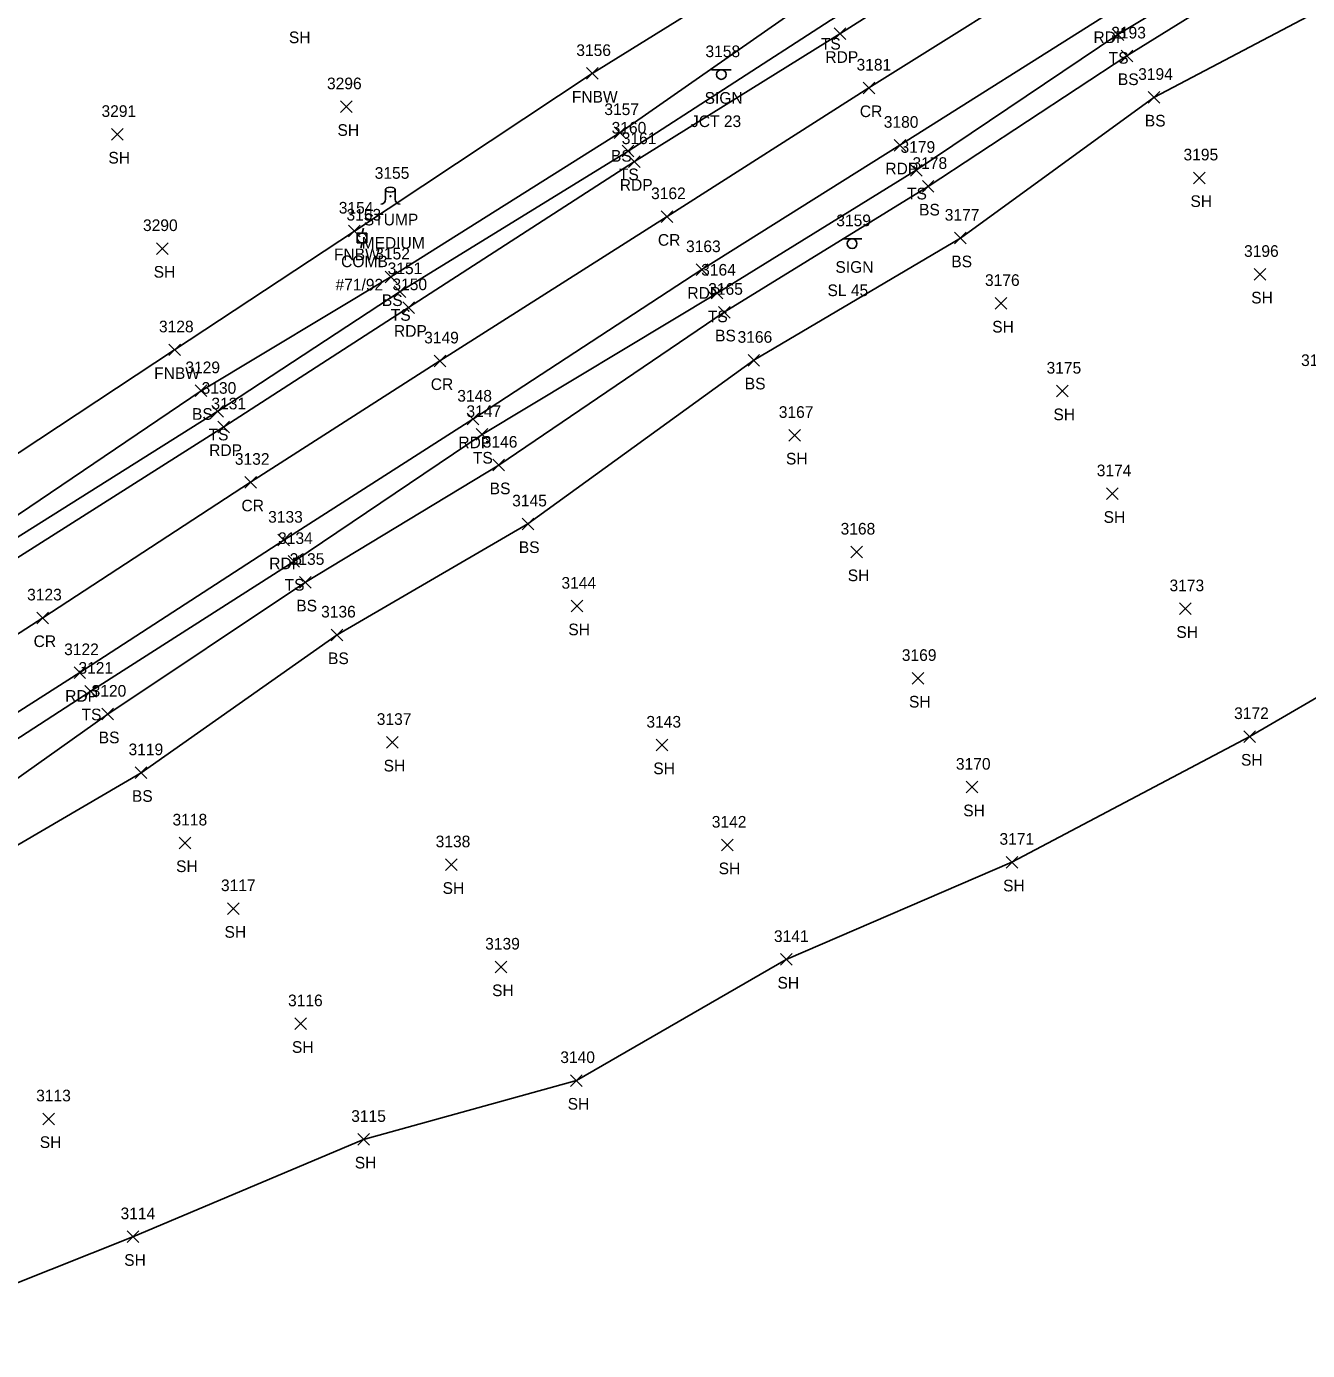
# Model space of a CAD drawing. Extents: x 1443590 to 1445966, y 578314 to 580556.
# Drawn here: x 1443728.1 to 1443948, y 578518.2 to 578745.5 of the extents above; entities that cross this region are included whole.
import ezdxf

# ---------------------------------------------------------------- set-up
doc = ezdxf.new("R2010")
doc.units = 0
for name, color, linetype in [('L_A', 7, 'Continuous'), ('L_C', 7, 'Continuous'), ('L_I', 7, 'Continuous'), ('L_TIC', 7, 'Continuous'), ('LELB', 7, 'Continuous'), ('LFNC', 7, 'Continuous'), ('LSOGP', 7, 'Continuous'), ('LTS', 7, 'Continuous'), ('P_A', 7, 'Continuous'), ('P_I', 7, 'Continuous'), ('P_TIC', 7, 'Continuous'), ('PET', 7, 'Continuous'), ('PRC', 7, 'Continuous'), ('S_A', 7, 'Continuous'), ('S_C', 7, 'Continuous'), ('S_I', 7, 'Continuous'), ('SSGN', 7, 'Continuous'), ('U_A', 7, 'Continuous'), ('U_C', 7, 'Continuous'), ('U_I', 7, 'Continuous'), ('UP', 7, 'Continuous')]:
    doc.layers.add(name, color=color, linetype=linetype)

msp = doc.modelspace()

# ---------------------------------------------------------------- linework, layer by layer
at = {"layer": 'L_TIC'}
for points in [[(1443914.45, 578743.08), (1443916.45, 578745.08)], [(1443916.45, 578743.08), (1443914.45, 578745.08)], [(1443916, 578739.41), (1443918, 578741.41)], [(1443918, 578739.41), (1443916, 578741.41)], [(1443824.24, 578736.4), (1443826.24, 578738.4)], [(1443826.24, 578736.4), (1443824.24, 578738.4)], [(1443920.62, 578732.3), (1443922.62, 578734.3)], [(1443922.62, 578732.3), (1443920.62, 578734.3)], [(1443782.01, 578730.69), (1443784.01, 578732.69)], [(1443784.01, 578730.69), (1443782.01, 578732.69)], [(1443742.69, 578725.94), (1443744.69, 578727.94)], [(1443744.69, 578725.94), (1443742.69, 578727.94)], [(1443829, 578726.26), (1443831, 578728.26)], [(1443831, 578726.26), (1443829, 578728.26)], [(1443830.38, 578723.08), (1443832.38, 578725.08)], [(1443832.38, 578723.08), (1443830.38, 578725.08)], [(1443879.84, 578719.78), (1443881.84, 578721.78)], [(1443881.84, 578719.78), (1443879.84, 578721.78)], [(1443928.4, 578718.48), (1443930.4, 578720.48)], [(1443930.4, 578718.48), (1443928.4, 578720.48)], [(1443881.88, 578717.02), (1443883.88, 578719.02)], [(1443883.88, 578717.02), (1443881.88, 578719.02)], [(1443783.42, 578709.35), (1443785.42, 578711.35)], [(1443785.42, 578709.35), (1443783.42, 578711.35)], [(1443887.41, 578708.13), (1443889.41, 578710.13)], [(1443889.41, 578708.13), (1443887.41, 578710.13)], [(1443750.46, 578706.35), (1443752.46, 578708.35)], [(1443752.46, 578706.35), (1443750.46, 578708.35)], [(1443938.83, 578701.92), (1443940.83, 578703.92)], [(1443940.83, 578701.92), (1443938.83, 578703.92)], [(1443789.68, 578701.48), (1443791.68, 578703.48)], [(1443791.68, 578701.48), (1443789.68, 578703.48)], [(1443791.24, 578698.95), (1443793.24, 578700.95)], [(1443793.24, 578698.95), (1443791.24, 578700.95)], [(1443845.66, 578698.7), (1443847.66, 578700.7)], [(1443847.66, 578698.7), (1443845.66, 578700.7)], [(1443846.87, 578695.41), (1443848.87, 578697.41)], [(1443848.87, 578695.41), (1443846.87, 578697.41)], [(1443894.38, 578696.93), (1443896.38, 578698.93)], [(1443896.38, 578696.93), (1443894.38, 578698.93)], [(1443752.55, 578688.96), (1443754.55, 578690.96)], [(1443754.55, 578688.96), (1443752.55, 578690.96)], [(1443851.96, 578687.17), (1443853.96, 578689.17)], [(1443853.96, 578687.17), (1443851.96, 578689.17)], [(1443757.09, 578681.95), (1443759.09, 578683.95)], [(1443759.09, 578681.95), (1443757.09, 578683.95)], [(1443904.9, 578681.88), (1443906.9, 578683.88)], [(1443906.9, 578681.88), (1443904.9, 578683.88)], [(1443759.96, 578678.42), (1443761.96, 578680.42)], [(1443761.96, 578678.42), (1443759.96, 578680.42)], [(1443805.33, 578674.43), (1443807.33, 578676.43)], [(1443807.33, 578674.43), (1443805.33, 578676.43)], [(1443858.98, 578674.28), (1443860.98, 578676.28)], [(1443860.98, 578674.28), (1443858.98, 578676.28)], [(1443808.17, 578669.17), (1443810.17, 578671.17)], [(1443810.17, 578669.17), (1443808.17, 578671.17)], [(1443913.5, 578664.26), (1443915.5, 578666.26)], [(1443915.5, 578664.26), (1443913.5, 578666.26)], [(1443813.18, 578659.08), (1443815.18, 578661.08)], [(1443815.18, 578659.08), (1443813.18, 578661.08)], [(1443869.59, 578654.25), (1443871.59, 578656.25)], [(1443871.59, 578654.25), (1443869.59, 578656.25)], [(1443773.01, 578652.63), (1443775.01, 578654.63)], [(1443775.01, 578652.63), (1443773.01, 578654.63)], [(1443774.99, 578649.05), (1443776.99, 578651.05)], [(1443776.99, 578649.05), (1443774.99, 578651.05)], [(1443821.63, 578644.96), (1443823.63, 578646.96)], [(1443823.63, 578644.96), (1443821.63, 578646.96)], [(1443925.99, 578644.52), (1443927.99, 578646.52)], [(1443927.99, 578644.52), (1443925.99, 578646.52)], [(1443780.43, 578640.01), (1443782.43, 578642.01)], [(1443782.43, 578640.01), (1443780.43, 578642.01)], [(1443880.11, 578632.56), (1443882.11, 578634.56)], [(1443882.11, 578632.56), (1443880.11, 578634.56)], [(1443738.16, 578630.36), (1443740.16, 578632.36)], [(1443740.16, 578630.36), (1443738.16, 578632.36)], [(1443741.08, 578626.42), (1443743.08, 578628.42)], [(1443743.08, 578626.42), (1443741.08, 578628.42)], [(1443937.08, 578622.58), (1443939.08, 578624.58)], [(1443939.08, 578622.58), (1443937.08, 578624.58)], [(1443789.93, 578621.58), (1443791.93, 578623.58)], [(1443791.93, 578621.58), (1443789.93, 578623.58)], [(1443836.21, 578621.11), (1443838.21, 578623.11)], [(1443838.21, 578621.11), (1443836.21, 578623.11)], [(1443746.78, 578616.37), (1443748.78, 578618.37)], [(1443748.78, 578616.37), (1443746.78, 578618.37)], [(1443889.41, 578613.89), (1443891.41, 578615.89)], [(1443891.41, 578613.89), (1443889.41, 578615.89)], [(1443754.31, 578604.31), (1443756.31, 578606.31)], [(1443756.31, 578604.31), (1443754.31, 578606.31)], [(1443847.43, 578603.94), (1443849.43, 578605.94)], [(1443849.43, 578603.94), (1443847.43, 578605.94)], [(1443800.05, 578600.57), (1443802.05, 578602.57)], [(1443802.05, 578600.57), (1443800.05, 578602.57)], [(1443896.25, 578601), (1443898.25, 578603)], [(1443898.25, 578601), (1443896.25, 578603)], [(1443762.62, 578593.04), (1443764.62, 578595.04)], [(1443764.62, 578593.04), (1443762.62, 578595.04)], [(1443857.53, 578584.31), (1443859.53, 578586.31)], [(1443859.53, 578584.31), (1443857.53, 578586.31)], [(1443808.55, 578583.01), (1443810.55, 578585.01)], [(1443810.55, 578583.01), (1443808.55, 578585.01)], [(1443774.19, 578573.28), (1443776.19, 578575.28)], [(1443776.19, 578573.28), (1443774.19, 578575.28)], [(1443821.52, 578563.53), (1443823.52, 578565.53)], [(1443823.52, 578563.53), (1443821.52, 578565.53)], [(1443730.91, 578556.95), (1443732.91, 578558.95)], [(1443732.91, 578556.95), (1443730.91, 578558.95)], [(1443784.98, 578553.43), (1443786.98, 578555.43)], [(1443786.98, 578553.43), (1443784.98, 578555.43)], [(1443745.4, 578536.72), (1443747.4, 578538.72)], [(1443747.4, 578536.72), (1443745.4, 578538.72)]]:
    msp.add_lwpolyline(points, dxfattribs=at)
at = {"layer": 'LELB'}
for points in [[(1443615.53, 578549.09), (1443647.15, 578571.87), (1443656.71, 578577.24), (1443699.78, 578605.86), (1443739.16, 578631.36), (1443774.01, 578653.63), (1443806.33, 578675.43), (1443846.66, 578699.7), (1443880.84, 578720.78), (1443915.45, 578744.08), (1443953.64, 578767.01), (1443986.4, 578787.39), (1444018.89, 578809.07), (1444030.21, 578814.65), (1444042.78, 578823.31), (1444045.84, 578825.91), (1444071.11, 578843.04), (1444083.63, 578848.63), (1444101.33, 578858.93), (1444132.81, 578873.64), (1444159.48, 578890.92), (1444189.04, 578910.16), (1444210.73, 578922.71), (1444214.87, 578926.32)], [(1443598.08, 578578.97), (1443630.15, 578597.86), (1443636.56, 578601.95), (1443682.3, 578633.7), (1443721.18, 578657.98), (1443758.09, 578682.95), (1443790.68, 578702.48), (1443830, 578727.26), (1443864.08, 578751.06), (1443899.99, 578773.27), (1443935.63, 578795.8), (1443970.37, 578818.04), (1444002.82, 578839.42), (1444013.71, 578847.8), (1444018.65, 578851.29), (1444030.07, 578858.77)], [(1443617.38, 578545.93), (1443649.59, 578568.34), (1443659.37, 578572.13), (1443703.15, 578599.79), (1443742.08, 578627.42), (1443775.99, 578650.05), (1443809.17, 578670.17), (1443847.87, 578696.41), (1443882.88, 578718.02), (1443917, 578740.41), (1443955.43, 578764.28), (1443988.08, 578784.83), (1444022, 578804.82), (1444030.48, 578811.54), (1444041.56, 578818.92), (1444047.79, 578822.82), (1444063.67, 578832.31)], [(1443599.26, 578576.43), (1443630.85, 578596.23), (1443637.73, 578600.06), (1443684.16, 578630.63), (1443722.9, 578655.5), (1443760.96, 578679.42), (1443792.24, 578699.95), (1443831.38, 578724.08), (1443866.05, 578746.5), (1443902.3, 578768.55), (1443938.52, 578791.48), (1443973.38, 578813.08)], [(1443707.24, 578593.68), (1443747.78, 578617.37), (1443781.43, 578641.01), (1443814.18, 578660.08), (1443852.96, 578688.17), (1443888.41, 578709.13), (1443921.62, 578733.3), (1443961.2, 578754.18), (1443994.65, 578773), (1444028.44, 578794.43), (1444032.53, 578801.75)]]:
    msp.add_lwpolyline(points, dxfattribs=at)
at = {"layer": 'LFNC'}
msp.add_lwpolyline([(1443632.19, 578609.42), (1443678.23, 578640.34), (1443716.84, 578665.76), (1443753.55, 578689.96), (1443784.42, 578710.35), (1443825.24, 578737.4), (1443860.1, 578759.1), (1443895.87, 578781.95), (1443931.05, 578803.95), (1443965.66, 578826.05), (1443995.74, 578844.91)], dxfattribs=at)
at = {"layer": 'LSOGP'}
msp.add_lwpolyline([(1443697.37, 578518.18), (1443746.4, 578537.72), (1443785.98, 578554.43), (1443822.53, 578564.53), (1443858.53, 578585.31), (1443897.25, 578602), (1443938.08, 578623.58), (1443972.29, 578643.52)], dxfattribs=at)
at = {"layer": 'LTS'}
for p, q in [((1443789.75, 578717.46), (1443789.75, 578715.8)), ((1443790.58, 578716.32), (1443790.58, 578716.32)), ((1443790.58, 578716.32), (1443790.58, 578716.32)), ((1443790.58, 578716.3), (1443790.58, 578716.3)), ((1443791.42, 578717.3), (1443791.42, 578717.46)), ((1443791.42, 578717.46), (1443791.42, 578715.8))]:
    msp.add_line(p, q, dxfattribs=at)
msp.add_circle((1443790.58, 578716.32), 0.0833, dxfattribs=at)
for centre, start, end in [((1443788.92, 578715.8), 270, 360), ((1443792.25, 578715.8), 180, 270)]:
    msp.add_arc(centre, 0.833, start, end, dxfattribs=at)
msp.add_ellipse((1443790.58, 578717.46), major_axis=(-0.833, 0), ratio=0.5, dxfattribs=at)
at = {"layer": 'P_TIC'}
for points in [[(1443866.74, 578743.22), (1443868.74, 578745.22)], [(1443868.74, 578743.22), (1443866.74, 578745.22)], [(1443871.72, 578733.91), (1443873.72, 578735.91)], [(1443873.72, 578733.91), (1443871.72, 578735.91)], [(1443877.04, 578724.08), (1443879.04, 578726.08)], [(1443879.04, 578724.08), (1443877.04, 578726.08)], [(1443831.46, 578721.27), (1443833.46, 578723.27)], [(1443833.46, 578721.27), (1443831.46, 578723.27)], [(1443837.06, 578711.83), (1443839.06, 578713.83)], [(1443839.06, 578711.83), (1443837.06, 578713.83)], [(1443843.06, 578702.73), (1443845.06, 578704.73)], [(1443845.06, 578702.73), (1443843.06, 578704.73)], [(1443792.7, 578696.2), (1443794.7, 578698.2)], [(1443794.7, 578696.2), (1443792.7, 578698.2)], [(1443798.08, 578687.06), (1443800.08, 578689.06)], [(1443800.08, 578687.06), (1443798.08, 578689.06)], [(1443803.75, 578677.07), (1443805.75, 578679.07)], [(1443805.75, 578677.07), (1443803.75, 578679.07)], [(1443760.98, 578675.74), (1443762.98, 578677.74)], [(1443762.98, 578675.74), (1443760.98, 578677.74)], [(1443765.58, 578666.23), (1443767.58, 578668.23)], [(1443767.58, 578666.23), (1443765.58, 578668.23)], [(1443771.29, 578656.29), (1443773.29, 578658.29)], [(1443773.29, 578656.29), (1443771.29, 578658.29)], [(1443729.92, 578642.94), (1443731.92, 578644.94)], [(1443731.92, 578642.94), (1443729.92, 578644.94)], [(1443736.28, 578633.55), (1443738.28, 578635.55)], [(1443738.28, 578633.55), (1443736.28, 578635.55)]]:
    msp.add_lwpolyline(points, dxfattribs=at)
at = {"layer": 'PET'}
for points in [[(1443601.36, 578573.38), (1443632.23, 578593.39), (1443639.99, 578598.09), (1443685.58, 578628.02), (1443724.74, 578653.09), (1443761.98, 578676.74), (1443793.7, 578697.2), (1443832.46, 578722.27), (1443867.74, 578744.22), (1443903.66, 578767.03), (1443939.74, 578789.58), (1443974.31, 578811.25), (1444005.54, 578830.37), (1444024.78, 578842.02), (1444070.83, 578869.64), (1444088.82, 578880.14), (1444118.02, 578897.28), (1444147.48, 578914.76), (1444176.13, 578931.32), (1444203.82, 578947.29), (1444208.88, 578939.04), (1444214.07, 578930.35)], [(1443612.4, 578554.37), (1443645.04, 578575.45), (1443657.24, 578583.2), (1443697.44, 578609.18), (1443737.28, 578634.55), (1443772.29, 578657.29), (1443804.75, 578678.07), (1443844.06, 578703.73), (1443878.04, 578725.08), (1443913.76, 578747.61), (1443950.95, 578770.86), (1443984.55, 578791.67), (1444017.37, 578812.19), (1444029.71, 578820.04), (1444042.88, 578828.09), (1444081.78, 578851.73), (1444099.65, 578862.29), (1444128.94, 578879.48), (1444156.82, 578896.17), (1444186.94, 578914.09), (1444214.07, 578930.35)]]:
    msp.add_lwpolyline(points, dxfattribs=at)
at = {"layer": 'PRC'}
msp.add_lwpolyline([(1443607.19, 578563.71), (1443645.74, 578588.68), (1443691.8, 578618.64), (1443730.92, 578643.94), (1443766.58, 578667.23), (1443799.08, 578688.06), (1443838.06, 578712.83), (1443872.72, 578734.91), (1443908.54, 578757.41), (1443944.72, 578780.26), (1443979.55, 578801.84), (1444011.31, 578821.61), (1444031.47, 578833.87), (1444076.05, 578860.79), (1444093.92, 578871.67), (1444123.23, 578888.92), (1444152.19, 578905.95), (1444180.96, 578922.73), (1444208.88, 578939.04)], dxfattribs=at)
at = {"layer": 'SSGN'}
for p, q in [((1443845.72, 578738.05), (1443849.06, 578738.05)), ((1443847.37, 578737.22), (1443847.37, 578737.22)), ((1443868.18, 578709.03), (1443871.51, 578709.03)), ((1443869.83, 578708.2), (1443869.83, 578708.2))]:
    msp.add_line(p, q, dxfattribs=at)
for centre in [(1443847.37, 578737.22), (1443869.83, 578708.2)]:
    msp.add_circle(centre, 0.833, dxfattribs=at)
at = {"layer": 'UP'}
for p, q in [((1443785.98, 578710.82), (1443785.73, 578709.99)), ((1443784.9, 578708.32), (1443784.9, 578709.99)), ((1443784.9, 578709.99), (1443786.56, 578709.99)), ((1443785.73, 578709.15), (1443785.73, 578709.15)), ((1443786.56, 578709.99), (1443786.56, 578708.32)), ((1443786.56, 578708.32), (1443784.9, 578708.32)), ((1443785.48, 578707.49), (1443785.73, 578708.32))]:
    msp.add_line(p, q, dxfattribs=at)
msp.add_circle((1443785.73, 578709.15), 0.833, dxfattribs=at)

# ---------------------------------------------------------------- texts
at = {"layer": 'L_A'}
for s, p in [('SH', (1443773.16, 578742.6)), ('TS', (1443864.46, 578741.5)), ('TS', (1443913.86, 578739.08)), ('BS', (1443915.44, 578735.41)), ('FNBW', (1443821.72, 578732.4)), ('BS', (1443920.06, 578728.3)), ('SH', (1443781.5, 578726.69)), ('BS', (1443828.44, 578722.26)), ('SH', (1443742.18, 578721.94)), ('TS', (1443829.79, 578719.08)), ('TS', (1443879.25, 578715.78)), ('SH', (1443927.89, 578714.48)), ('STUMP', (1443786.01, 578711.32)), ('BS', (1443881.32, 578713.02)), ('FNBW', (1443780.89, 578705.35)), ('BS', (1443886.85, 578704.13)), ('SH', (1443749.95, 578702.35)), ('BS', (1443789.12, 578697.48)), ('SH', (1443938.32, 578697.92)), ('TS', (1443790.65, 578694.95)), ('TS', (1443845.07, 578694.7)), ('SH', (1443893.87, 578692.93)), ('BS', (1443846.31, 578691.41)), ('FNBW', (1443750.03, 578684.96)), ('BS', (1443851.4, 578683.17)), ('BS', (1443756.53, 578677.95)), ('SH', (1443904.38, 578677.88)), ('TS', (1443759.37, 578674.42)), ('TS', (1443804.74, 578670.43)), ('SH', (1443858.47, 578670.28)), ('BS', (1443807.62, 578665.17)), ('SH', (1443912.99, 578660.26)), ('BS', (1443812.62, 578655.08)), ('SH', (1443869.08, 578650.25)), ('TS', (1443772.42, 578648.63)), ('BS', (1443774.43, 578645.05)), ('SH', (1443821.12, 578640.96)), ('SH', (1443925.48, 578640.52)), ('BS', (1443779.88, 578636.01)), ('SH', (1443879.59, 578628.56)), ('TS', (1443737.57, 578626.36)), ('BS', (1443740.52, 578622.42)), ('SH', (1443936.57, 578618.58)), ('SH', (1443789.42, 578617.58)), ('SH', (1443835.7, 578617.11)), ('BS', (1443746.22, 578612.37)), ('SH', (1443888.9, 578609.89)), ('SH', (1443753.8, 578600.31)), ('SH', (1443846.92, 578599.94)), ('SH', (1443799.54, 578596.57)), ('SH', (1443895.74, 578597)), ('SH', (1443762.11, 578589.04)), ('SH', (1443857.02, 578580.31)), ('SH', (1443808.04, 578579.01)), ('SH', (1443773.68, 578569.28)), ('SH', (1443821.01, 578559.53)), ('SH', (1443730.4, 578552.95)), ('SH', (1443784.47, 578549.43)), ('SH', (1443744.89, 578532.72))]:
    msp.add_text(s, height=2, dxfattribs=at).set_placement(p)
at = {"layer": 'L_C'}
msp.add_text('MEDIUM', height=2, dxfattribs=at).set_placement((1443785.64, 578707.32))
at = {"layer": 'L_I'}
for s, p in [('3193', (1443914.3, 578743.41)), ('3156', (1443822.49, 578740.4)), ('3194', (1443918.92, 578736.3)), ('3296', (1443779.7, 578734.69)), ('3291', (1443741, 578729.94)), ('3157', (1443827.3, 578730.26)), ('3160', (1443828.55, 578727.08)), ('3179', (1443878.14, 578723.78)), ('3195', (1443926.71, 578722.48)), ('3178', (1443880.19, 578721.02)), ('3155', (1443787.89, 578719.32)), ('3154', (1443781.72, 578713.35)), ('3177', (1443885.72, 578712.13)), ('3290', (1443748.12, 578710.35)), ('3152', (1443787.98, 578705.48)), ('3196', (1443937.09, 578705.92)), ('3151', (1443790.11, 578702.95)), ('3164', (1443843.92, 578702.7)), ('3176', (1443892.63, 578700.93)), ('3165', (1443845.13, 578699.41)), ('3128', (1443750.86, 578692.96)), ('3166', (1443850.17, 578691.17)), ('3129', (1443755.39, 578685.95)), ('3197', (1443946.88, 578687.18)), ('3175', (1443903.2, 578685.88)), ('3130', (1443758.18, 578682.42)), ('3147', (1443803.64, 578678.43)), ('3167', (1443857.24, 578678.28)), ('3146', (1443806.43, 578673.17)), ('3174', (1443911.81, 578668.26)), ('3145', (1443811.49, 578663.08)), ('3134', (1443771.31, 578656.63)), ('3168', (1443867.85, 578658.25)), ('3135', (1443773.3, 578653.05)), ('3144', (1443819.94, 578648.96)), ('3173', (1443924.3, 578648.52)), ('3136', (1443778.69, 578644.01)), ('3169', (1443878.36, 578636.56)), ('3121', (1443737.04, 578634.36)), ('3120', (1443739.3, 578630.42)), ('3137', (1443788.24, 578625.58)), ('3143', (1443834.52, 578625.11)), ('3172', (1443935.39, 578626.58)), ('3119', (1443745.64, 578620.37)), ('3170', (1443887.64, 578617.89)), ('3118', (1443753.19, 578608.31)), ('3142', (1443845.74, 578607.94)), ('3138', (1443798.35, 578604.57)), ('3171', (1443895.12, 578605)), ('3117', (1443761.5, 578597.04)), ('3141', (1443856.41, 578588.31)), ('3139', (1443806.85, 578587.01)), ('3116', (1443773.01, 578577.28)), ('3140', (1443819.74, 578567.53)), ('3113', (1443729.79, 578560.95)), ('3115', (1443783.86, 578557.43)), ('3114', (1443744.27, 578540.72))]:
    msp.add_text(s, height=2, dxfattribs=at).set_placement(p)
at = {"layer": 'P_A'}
for s, p in [('RDP', (1443911.25, 578742.61)), ('RDP', (1443865.23, 578739.22)), ('CR', (1443871.15, 578729.91)), ('RDP', (1443875.53, 578720.08)), ('RDP', (1443829.95, 578717.27)), ('CR', (1443836.49, 578707.83)), ('RDP', (1443841.55, 578698.73)), ('RDP', (1443791.19, 578692.2)), ('CR', (1443797.51, 578683.06)), ('RDP', (1443802.24, 578673.07)), ('RDP', (1443759.47, 578671.74)), ('CR', (1443765.02, 578662.23)), ('RDP', (1443769.78, 578652.29)), ('CR', (1443729.35, 578638.94)), ('RDP', (1443734.77, 578629.55))]:
    msp.add_text(s, height=2, dxfattribs=at).set_placement(p)
at = {"layer": 'P_I'}
for s, p in [('3181', (1443870.59, 578737.91)), ('3180', (1443875.26, 578728.08)), ('3161', (1443830.29, 578725.27)), ('3162', (1443835.32, 578715.83)), ('3163', (1443841.32, 578706.73)), ('3150', (1443790.93, 578700.2)), ('3149', (1443796.38, 578691.06)), ('3131', (1443759.86, 578679.74)), ('3148', (1443802.06, 578681.07)), ('3132', (1443763.89, 578670.23)), ('3133', (1443769.6, 578660.29)), ('3123', (1443728.23, 578646.94)), ('3122', (1443734.59, 578637.55))]:
    msp.add_text(s, height=2, dxfattribs=at).set_placement(p)
at = {"layer": 'S_A'}
for p in [(1443844.51, 578732.2), (1443866.96, 578703.18)]:
    msp.add_text('SIGN', height=2, dxfattribs=at).set_placement(p)
at = {"layer": 'S_C'}
for s, p in [('JCT 23', (1443842.17, 578728.2)), ('SL 45', (1443865.6, 578699.18))]:
    msp.add_text(s, height=2, dxfattribs=at).set_placement(p)
at = {"layer": 'S_I'}
for s, p in [('3158', (1443844.66, 578740.2)), ('3159', (1443867.11, 578711.18))]:
    msp.add_text(s, height=2, dxfattribs=at).set_placement(p)
at = {"layer": 'U_A'}
msp.add_text('COMB', height=2, dxfattribs=at).set_placement((1443782.12, 578704.15))
at = {"layer": 'U_C'}
msp.add_text('#71/92', height=2, dxfattribs=at).set_placement((1443781.16, 578700.15))
at = {"layer": 'U_I'}
msp.add_text('3153', height=2, dxfattribs=at).set_placement((1443783.04, 578712.15))

doc.saveas('drawing.dxf')
